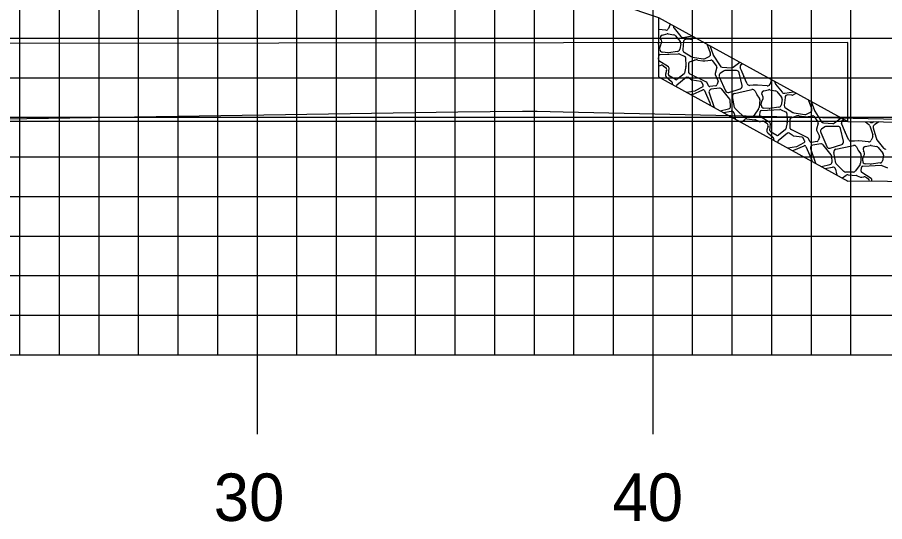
# Model space of a CAD drawing. Extents: x 856323 to 856666, y 364765 to 364985.
# Drawn here: x 856512.7 to 856534.62, y 364824.09 to 364836.83 of the extents above; entities that cross this region are included whole.
import ezdxf

# ---------------------------------------------------------------- set-up
doc = ezdxf.new("R2010")
doc.units = 0
for name, color, linetype in [('D_Drainage_Culvert', 7, 'Continuous'), ('D_Roadway_Centerline', 7, 'Continuous'), ('D_Roadway_FinishedGrade', 7, 'Continuous'), ('D_Roadway_SlopeLines', 7, 'Continuous'), ('H_V ANNOTATION', 7, 'Continuous'), ('MAJOR', 7, 'Continuous'), ('MINOR', 7, 'Continuous'), ('S_Roadway_Centerline', 7, 'Continuous')]:
    doc.layers.add(name, color=color, linetype=linetype)

msp = doc.modelspace()

# ---------------------------------------------------------------- linework, layer by layer
at = {"layer": 'D_Drainage_Culvert'}
msp.add_line((856533.694, 364834.192), (856476.17, 364834.192), dxfattribs=at)
msp.add_lwpolyline([(856533.694, 364834.192), (856533.691, 364836.192), (856476.17, 364836.121)], dxfattribs=at)
at = {"layer": 'D_Roadway_Centerline'}
msp.add_lwpolyline([(856476.17, 364847.458), (856483.623, 364847.116), (856488.768, 364846.88), (856491.27, 364846.765), (856496.768, 364846.512), (856500.528, 364845.572), (856508.768, 364843.512), (856509.507, 364843.328), (856509.84, 364843.244), (856518.287, 364840.401), (856528.903, 364836.827)], dxfattribs=at)
at = {"layer": 'D_Roadway_FinishedGrade'}
for p, q in [((856529.193, 364836.628), (856529.156, 364836.544)), ((856529.273, 364836.623), (856529.287, 364836.573)), ((856529.088, 364836.503), (856528.903, 364836.518)), ((856529.002, 364836.38), (856529.126, 364836.408)), ((856529.153, 364836.408), (856529.292, 364836.383)), ((856529.3, 364836.55), (856529.466, 364836.344)), ((856529.332, 364836.36), (856529.452, 364836.217)), ((856529.531, 364836.319), (856529.755, 364836.358)), ((856528.904, 364836.149), (856528.903, 364836.131)), ((856528.953, 364836.112), (856528.984, 364836.182)), ((856528.978, 364836.248), (856528.96, 364836.276)), ((856529.467, 364836.161), (856529.443, 364836.022)), ((856529.54, 364836.213), (856529.522, 364836.011)), ((856529.714, 364836.271), (856529.611, 364836.275)), ((856529.826, 364836.319), (856529.747, 364836.279)), ((856530.217, 364835.924), (856530.135, 364836.149)), ((856528.941, 364836.019), (856528.948, 364836.091)), ((856528.944, 364835.885), (856529.411, 364835.907)), ((856529.14, 364835.932), (856529.003, 364835.944)), ((856529.385, 364835.966), (856529.156, 364835.933)), ((856529.554, 364835.947), (856529.734, 364835.835)), ((856530.202, 364836.112), (856530.283, 364835.883)), ((856528.903, 364835.772), (856528.911, 364835.854)), ((856529.157, 364835.575), (856528.917, 364835.725)), ((856529.427, 364835.904), (856529.57, 364835.84)), ((856529.59, 364835.81), (856529.596, 364835.59)), ((856529.692, 364835.701), (856529.815, 364835.742)), ((856529.76, 364835.825), (856530.042, 364835.781)), ((856529.898, 364835.749), (856530.023, 364835.728)), ((856530.075, 364835.727), (856530.232, 364835.749)), ((856530.084, 364835.788), (856530.184, 364835.839)), ((856530.264, 364835.736), (856530.372, 364835.594)), ((856530.29, 364835.869), (856530.461, 364835.6)), ((856530.793, 364835.568), (856530.958, 364835.697)), ((856528.922, 364835.605), (856528.971, 364835.615)), ((856529.023, 364835.605), (856529.083, 364835.563)), ((856529.11, 364835.488), (856529.082, 364835.392)), ((856529.158, 364835.379), (856529.173, 364835.543)), ((856529.596, 364835.582), (856529.561, 364835.42)), ((856529.673, 364835.429), (856529.669, 364835.668)), ((856530.378, 364835.564), (856530.336, 364835.409)), ((856530.547, 364835.468), (856530.465, 364835.412)), ((856530.515, 364835.568), (856530.747, 364835.554)), ((856530.877, 364835.48), (856530.586, 364835.481)), ((856531.001, 364835.482), (856530.971, 364835.554)), ((856531.059, 364835.339), (856531.001, 364835.482)), ((856531.008, 364835.643), (856531.035, 364835.654)), ((856529.103, 364835.321), (856529.236, 364835.208)), ((856529.334, 364835.253), (856529.175, 364835.347)), ((856529.602, 364835.309), (856529.369, 364835.112)), ((856529.55, 364835.401), (856529.373, 364835.256)), ((856529.744, 364835.243), (856529.643, 364835.312)), ((856530.118, 364835.193), (856529.692, 364835.399)), ((856530.338, 364835.385), (856530.409, 364835.233)), ((856530.442, 364835.328), (856530.6, 364834.969)), ((856531.018, 364835.104), (856530.943, 364835.427)), ((856531.147, 364835.148), (856531.06, 364835.336)), ((856529.257, 364835.137), (856529.256, 364835.132)), ((856529.356, 364835.085), (856529.357, 364835.077)), ((856529.972, 364835.206), (856529.758, 364835.237)), ((856529.838, 364834.975), (856530.02, 364835.071)), ((856530.035, 364835.117), (856529.997, 364835.188)), ((856530.169, 364835.098), (856530.135, 364835.176)), ((856530.352, 364835.1), (856530.205, 364835.078)), ((856530.444, 364835.037), (856530.239, 364835.009)), ((856530.41, 364835.207), (856530.379, 364835.122)), ((856531.297, 364835.111), (856531.211, 364835.108)), ((856531.399, 364835.114), (856531.297, 364835.111)), ((856531.651, 364835.094), (856531.407, 364835.114)), ((856531.756, 364835.218), (856531.719, 364835.134)), ((856531.836, 364835.214), (856531.85, 364835.164)), ((856531.863, 364835.14), (856532.029, 364834.934)), ((856529.615, 364834.935), (856529.828, 364834.972)), ((856529.725, 364834.875), (856529.752, 364834.876)), ((856529.764, 364834.879), (856530.023, 364834.993)), ((856530.068, 364834.975), (856530.203, 364834.668)), ((856530.184, 364834.919), (856530.311, 364834.552)), ((856530.705, 364834.761), (856530.507, 364835.011)), ((856530.683, 364834.931), (856530.972, 364835.023)), ((856530.828, 364834.553), (856530.774, 364834.824)), ((856530.827, 364834.904), (856531.232, 364834.993)), ((856531.232, 364834.993), (856531.268, 364835.001)), ((856531.345, 364834.964), (856531.387, 364834.878)), ((856531.394, 364834.866), (856531.453, 364834.789)), ((856531.541, 364834.838), (856531.522, 364834.867)), ((856531.565, 364834.971), (856531.689, 364834.998)), ((856531.716, 364834.999), (856531.855, 364834.973)), ((856531.895, 364834.95), (856532.015, 364834.808)), ((856532.094, 364834.91), (856532.318, 364834.949)), ((856532.276, 364834.862), (856532.174, 364834.866)), ((856532.389, 364834.91), (856532.31, 364834.87)), ((856530.205, 364834.663), (856530.22, 364834.602)), ((856530.729, 364834.586), (856530.719, 364834.723)), ((856531.467, 364834.74), (856531.446, 364834.548)), ((856531.503, 364834.61), (856531.51, 364834.682)), ((856531.516, 364834.703), (856531.547, 364834.773)), ((856532.03, 364834.752), (856532.005, 364834.612)), ((856532.103, 364834.804), (856532.085, 364834.602)), ((856532.78, 364834.514), (856532.698, 364834.74)), ((856532.765, 364834.703), (856532.846, 364834.473)), ((856530.464, 364834.468), (856530.676, 364834.515)), ((856530.549, 364834.422), (856530.741, 364834.454)), ((856530.819, 364834.399), (856530.841, 364834.283)), ((856530.928, 364834.44), (856530.848, 364834.516)), ((856531.028, 364834.345), (856530.928, 364834.44)), ((856531.435, 364834.517), (856531.325, 364834.354)), ((856531.464, 364834.349), (856531.474, 364834.445)), ((856531.507, 364834.475), (856531.974, 364834.498)), ((856531.703, 364834.523), (856531.566, 364834.535)), ((856531.948, 364834.557), (856531.719, 364834.524)), ((856531.99, 364834.495), (856532.132, 364834.431)), ((856532.117, 364834.538), (856532.297, 364834.425)), ((856532.152, 364834.401), (856532.159, 364834.181)), ((856532.323, 364834.416), (856532.605, 364834.372)), ((856532.646, 364834.378), (856532.747, 364834.43)), ((856532.853, 364834.459), (856533.024, 364834.19)), ((856530.841, 364834.283), (856530.846, 364834.258)), ((856530.995, 364834.177), (856531.086, 364834.247)), ((856531.267, 364834.324), (856531.074, 364834.327)), ((856531.135, 364834.261), (856531.342, 364834.238)), ((856531.36, 364834.234), (856531.446, 364834.2)), ((856531.719, 364834.166), (856531.48, 364834.316)), ((856531.485, 364834.196), (856531.533, 364834.206)), ((856531.586, 364834.196), (856531.646, 364834.154)), ((856532.158, 364834.173), (856532.124, 364834.011)), ((856532.236, 364834.02), (856532.231, 364834.259)), ((856532.255, 364834.292), (856532.378, 364834.333)), ((856532.461, 364834.34), (856532.586, 364834.318)), ((856532.638, 364834.317), (856532.795, 364834.339)), ((856532.827, 364834.326), (856532.935, 364834.185)), ((856532.941, 364834.155), (856532.899, 364833.999)), ((856533.078, 364834.159), (856533.309, 364834.145)), ((856533.355, 364834.159), (856533.52, 364834.287)), ((856533.57, 364834.233), (856533.598, 364834.245)), ((856534.137, 364834.188), (856534.222, 364834.12)), ((856534.249, 364834.187), (856534.249, 364834.187)), ((856534.349, 364834.186), (856534.333, 364834.177)), ((856534.473, 364834.185), (856534.36, 364834.108)), ((856531.673, 364834.078), (856531.645, 364833.983)), ((856531.721, 364833.97), (856531.735, 364834.134)), ((856531.897, 364833.843), (856531.738, 364833.938)), ((856532.112, 364833.991), (856531.936, 364833.846)), ((856532.681, 364833.783), (856532.255, 364833.99)), ((856532.901, 364833.976), (856532.972, 364833.824)), ((856533.11, 364834.059), (856533.028, 364834.003)), ((856533.44, 364834.071), (856533.149, 364834.071)), ((856533.581, 364833.695), (856533.506, 364834.018)), ((856533.564, 364834.073), (856533.534, 364834.144)), ((856533.622, 364833.93), (856533.564, 364834.073)), ((856534.245, 364834.088), (856534.321, 364833.858)), ((856534.332, 364834.033), (856534.399, 364833.805)), ((856531.666, 364833.912), (856531.799, 364833.799)), ((856531.82, 364833.728), (856531.819, 364833.723)), ((856532.165, 364833.9), (856531.931, 364833.703)), ((856532.306, 364833.834), (856532.206, 364833.902)), ((856532.535, 364833.797), (856532.321, 364833.828)), ((856532.597, 364833.707), (856532.56, 364833.779)), ((856532.731, 364833.688), (856532.697, 364833.766)), ((856532.973, 364833.797), (856532.942, 364833.713)), ((856533.004, 364833.919), (856533.163, 364833.56)), ((856533.709, 364833.739), (856533.623, 364833.927)), ((856534.319, 364833.809), (856534.282, 364833.725)), ((856534.399, 364833.805), (856534.413, 364833.755)), ((856534.425, 364833.731), (856534.591, 364833.525)), ((856531.919, 364833.676), (856531.919, 364833.668)), ((856532.178, 364833.526), (856532.39, 364833.563)), ((856532.327, 364833.47), (856532.585, 364833.584)), ((856532.4, 364833.566), (856532.583, 364833.661)), ((856532.631, 364833.566), (856532.766, 364833.259)), ((856532.747, 364833.51), (856532.873, 364833.143)), ((856532.915, 364833.691), (856532.768, 364833.668)), ((856533.007, 364833.628), (856532.802, 364833.6)), ((856533.268, 364833.351), (856533.07, 364833.602)), ((856533.246, 364833.522), (856533.535, 364833.614)), ((856533.389, 364833.495), (856533.795, 364833.584)), ((856533.86, 364833.702), (856533.774, 364833.699)), ((856533.795, 364833.584), (856533.831, 364833.592)), ((856533.961, 364833.705), (856533.86, 364833.702)), ((856533.907, 364833.555), (856533.95, 364833.469)), ((856534.213, 364833.684), (856533.969, 364833.705)), ((856534.127, 364833.562), (856534.252, 364833.589)), ((856534.279, 364833.59), (856534.418, 364833.564)), ((856534.458, 364833.541), (856534.578, 364833.399)), ((856532.287, 364833.465), (856532.314, 364833.467)), ((856533.292, 364833.177), (856533.282, 364833.314)), ((856533.391, 364833.144), (856533.337, 364833.415)), ((856533.957, 364833.457), (856534.016, 364833.379)), ((856534.03, 364833.33), (856534.009, 364833.139)), ((856534.079, 364833.293), (856534.109, 364833.364)), ((856534.104, 364833.429), (856534.085, 364833.457)), ((856534.593, 364833.343), (856534.568, 364833.203)), ((856532.768, 364833.254), (856532.783, 364833.193)), ((856533.027, 364833.059), (856533.238, 364833.105)), ((856533.491, 364833.031), (856533.41, 364833.107)), ((856533.998, 364833.108), (856533.888, 364832.945)), ((856534.066, 364833.2), (856534.073, 364833.272)), ((856534.069, 364833.066), (856534.537, 364833.089)), ((856534.266, 364833.114), (856534.128, 364833.126)), ((856534.511, 364833.147), (856534.282, 364833.114)), ((856534.553, 364833.086), (856534.695, 364833.022)), ((856533.111, 364833.012), (856533.304, 364833.045)), ((856533.382, 364832.99), (856533.404, 364832.874)), ((856533.404, 364832.874), (856533.409, 364832.849)), ((856533.591, 364832.936), (856533.491, 364833.031)), ((856533.558, 364832.768), (856533.648, 364832.838)), ((856533.83, 364832.915), (856533.637, 364832.917)), ((856533.697, 364832.851), (856533.905, 364832.829)), ((856534.027, 364832.94), (856534.037, 364833.036)), ((856534.282, 364832.756), (856534.042, 364832.907)), ((856533.923, 364832.824), (856534.009, 364832.79)), ((856534.047, 364832.787), (856534.096, 364832.797)), ((856534.149, 364832.786), (856534.209, 364832.745)), ((856534.295, 364832.687), (856534.298, 364832.724))]:
    msp.add_line(p, q, dxfattribs=at)
for centre, radius, start, end in [((856529.13, 364836.655), 0.0684, 336.3884, 7.7757), ((856529.353, 364836.593), 0.0684, 196.194, 218.8878), ((856529.017, 364836.314), 0.0684, 102.3799, 213.4945), ((856529.094, 364836.571), 0.0684, 265.1565, 336.3884), ((856529.141, 364836.341), 0.0684, 79.6289, 102.3799), ((856529.28, 364836.315), 0.0684, 40.2205, 79.6289), ((856529.519, 364836.387), 0.0684, 218.8878, 279.8538), ((856528.836, 364836.156), 0.0684, 353.6734, 15.0307), ((856528.921, 364836.21), 0.0684, 336.3884, 33.4945), ((856529.4, 364836.173), 0.0684, 349.9353, 40.2205), ((856529.608, 364836.207), 0.0684, 87.759, 174.9435), ((856529.716, 364836.34), 0.0684, 267.759, 296.9783), ((856529.009, 364836.012), 0.0684, 174.5792, 265.0542), ((856529.016, 364836.084), 0.0684, 156.3884, 174.5792), ((856529.146, 364836), 0.0684, 265.0542, 278.2139), ((856529.375, 364836.034), 0.0684, 278.2139, 349.9353), ((856529.413, 364835.873), 0.0342, 65.8608, 92.7454), ((856529.59, 364836.005), 0.0684, 174.9435, 237.9695), ((856530.153, 364835.9), 0.0684, 297.1975, 20.0877), ((856528.935, 364835.754), 0.0342, 197.9909, 237.8666), ((856528.945, 364835.851), 0.0342, 92.7454, 173.8138), ((856529.556, 364835.809), 0.0342, 1.7042, 65.8608), ((856529.703, 364835.669), 0.0342, 108.5155, 180.9859), ((856529.771, 364835.892), 0.0684, 237.9695, 261.1196), ((856529.869, 364835.58), 0.171, 80.3276, 108.5155), ((856530.052, 364835.896), 0.171, 260.3276, 277.9584), ((856530.052, 364835.848), 0.0684, 261.1196, 297.1975), ((856530.237, 364835.715), 0.0342, 37.3338, 97.9584), ((856530.348, 364835.905), 0.0684, 199.4352, 212.488), ((856528.908, 364835.672), 0.0684, 265.2397, 281.5585), ((856528.984, 364835.548), 0.0684, 55.4834, 101.5585), ((856529.045, 364835.507), 0.0684, 343.6014, 55.4834), ((856529.139, 364835.546), 0.0342, 354.9435, 57.8666), ((856529.562, 364835.589), 0.0342, 348.1215, 1.7042), ((856530.345, 364835.573), 0.0342, 344.9548, 37.3338), ((856530.519, 364835.636), 0.0684, 212.488, 266.5979), ((856530.586, 364835.412), 0.0684, 89.9515, 124.6871), ((856530.751, 364835.622), 0.0684, 266.5979, 307.8384), ((856530.877, 364835.412), 0.0684, 13.0274, 89.9515), ((856531.035, 364835.58), 0.0684, 113.1469, 202.5342), ((856530.938, 364835.456), 0.0684, 22.1001, 22.5342), ((856529.148, 364835.373), 0.0684, 163.6014, 229.5603), ((856529.192, 364835.376), 0.0342, 174.9435, 239.3161), ((856529.351, 364835.282), 0.0342, 239.3161, 309.3926), ((856529.528, 364835.427), 0.0342, 309.3926, 348.1215), ((856529.624, 364835.283), 0.0342, 55.6218, 130.2011), ((856529.707, 364835.43), 0.0342, 180.9859, 244.1843), ((856530.369, 364835.4), 0.0342, 164.9548, 204.8803), ((856530.504, 364835.356), 0.0684, 124.6871, 203.8307), ((856531.122, 364835.365), 0.0684, 202.1001, 204.6651), ((856531.693, 364835.246), 0.0684, 336.3884, 7.7757), ((856529.192, 364835.156), 0.0684, 344.328, 49.5603), ((856529.391, 364835.086), 0.0342, 130.2011, 181.8446), ((856529.763, 364835.271), 0.0342, 235.6218, 261.6774), ((856529.967, 364835.172), 0.0342, 27.5039, 81.6774), ((856530.004, 364835.101), 0.0342, 297.5039, 27.5039), ((856530.103, 364835.162), 0.0342, 23.6254, 64.1843), ((856530.2, 364835.111), 0.0342, 203.6254, 278.7288), ((856530.347, 364835.134), 0.0342, 278.7288, 339.9401), ((856530.378, 364835.218), 0.0342, 339.9401, 24.8803), ((856530.454, 364834.969), 0.0684, 38.1718, 97.8011), ((856530.952, 364835.088), 0.0684, 287.6261, 13.0274), ((856531.209, 364835.177), 0.0684, 204.6651, 271.8446), ((856531.401, 364835.046), 0.0684, 85.1565, 91.8446), ((856531.656, 364835.162), 0.0684, 265.1565, 336.3884), ((856531.916, 364835.183), 0.0684, 196.194, 218.8878), ((856529.75, 364834.91), 0.0342, 272.567, 293.7886), ((856529.822, 364835.006), 0.0342, 279.9682, 297.5039), ((856530.037, 364834.962), 0.0342, 23.7886, 113.7886), ((856530.249, 364834.941), 0.0684, 97.8011, 199.0716), ((856530.663, 364834.997), 0.0684, 203.8307, 287.6261), ((856530.841, 364834.837), 0.0684, 102.451, 191.1515), ((856531.283, 364834.934), 0.0684, 25.9764, 102.451), ((856531.448, 364834.908), 0.0684, 205.9764, 217.5646), ((856531.579, 364834.904), 0.0684, 102.3799, 213.4945), ((856531.484, 364834.801), 0.0684, 336.3884, 33.4945), ((856531.704, 364834.932), 0.0684, 79.6289, 102.3799), ((856531.843, 364834.906), 0.0684, 40.2205, 79.6289), ((856532.082, 364834.977), 0.0684, 218.8878, 279.8538), ((856532.171, 364834.798), 0.0684, 87.759, 174.9435), ((856532.279, 364834.931), 0.0684, 267.759, 296.9783), ((856530.172, 364834.655), 0.0342, 13.983, 23.7886), ((856530.651, 364834.718), 0.0684, 4.1565, 38.1718), ((856531.399, 364834.747), 0.0684, 353.6734, 37.5646), ((856531.572, 364834.603), 0.0684, 174.5792, 265.0542), ((856531.578, 364834.675), 0.0684, 156.3884, 174.5792), ((856531.938, 364834.624), 0.0684, 278.2139, 349.9353), ((856531.963, 364834.764), 0.0684, 349.9353, 40.2205), ((856532.153, 364834.596), 0.0684, 174.9435, 237.9695), ((856530.661, 364834.581), 0.0684, 282.4402, 4.1565), ((856530.752, 364834.387), 0.0684, 10.6652, 99.567), ((856530.895, 364834.566), 0.0684, 191.1515, 226.4504), ((856531.378, 364834.555), 0.0684, 325.9996, 353.6734), ((856531.508, 364834.441), 0.0342, 92.7454, 173.8138), ((856531.709, 364834.591), 0.0684, 265.0542, 278.2139), ((856531.976, 364834.464), 0.0342, 65.8608, 92.7454), ((856532.118, 364834.4), 0.0342, 1.7042, 65.8608), ((856532.333, 364834.483), 0.0684, 237.9695, 261.1196), ((856532.615, 364834.439), 0.0684, 261.1196, 297.1975), ((856532.716, 364834.491), 0.0684, 297.1975, 20.0877), ((856532.911, 364834.496), 0.0684, 199.4352, 212.488), ((856531.037, 364834.123), 0.0684, 127.5119, 128.402), ((856531.075, 364834.395), 0.0684, 226.4504, 269.2665), ((856531.127, 364834.193), 0.0684, 83.8138, 127.5119), ((856531.268, 364834.392), 0.0684, 269.2665, 325.9996), ((856531.335, 364834.17), 0.0684, 68.319, 83.8138), ((856531.471, 364834.263), 0.0684, 248.319, 281.5585), ((856531.498, 364834.345), 0.0342, 173.8138, 237.8666), ((856531.547, 364834.139), 0.0684, 55.4834, 101.5585), ((856531.607, 364834.098), 0.0684, 343.6014, 55.4834), ((856531.701, 364834.137), 0.0342, 354.9435, 57.8666), ((856532.125, 364834.18), 0.0342, 348.1215, 1.7042), ((856532.266, 364834.259), 0.0342, 108.5155, 180.9859), ((856532.432, 364834.171), 0.171, 80.3276, 108.5155), ((856532.614, 364834.487), 0.171, 260.3276, 277.9584), ((856532.8, 364834.306), 0.0342, 37.3338, 97.9584), ((856532.908, 364834.164), 0.0342, 344.9548, 37.3338), ((856533.082, 364834.227), 0.0684, 212.488, 266.5979), ((856533.313, 364834.213), 0.0684, 266.5979, 307.8384), ((856533.597, 364834.171), 0.0684, 113.1469, 202.5342), ((856534.298, 364834.235), 0.0684, 225.2486, 301.0205), ((856531.711, 364833.964), 0.0684, 163.6014, 229.5603), ((856531.755, 364833.967), 0.0342, 174.9435, 239.3161), ((856532.091, 364834.018), 0.0342, 309.3926, 348.1215), ((856532.27, 364834.02), 0.0342, 180.9859, 244.1843), ((856532.932, 364833.99), 0.0342, 164.9548, 204.8803), ((856533.067, 364833.946), 0.0684, 124.6871, 203.8307), ((856533.149, 364834.003), 0.0684, 89.9515, 124.6871), ((856533.44, 364834.003), 0.0684, 13.0274, 89.9515), ((856533.501, 364834.047), 0.0684, 22.1001, 22.5342), ((856534.18, 364834.067), 0.0684, 18.3151, 51.3282), ((856534.398, 364834.052), 0.0684, 124.1631, 196.194), ((856531.754, 364833.747), 0.0684, 344.328, 49.5603), ((856531.914, 364833.873), 0.0342, 239.3161, 309.3926), ((856532.187, 364833.874), 0.0342, 55.6218, 130.2011), ((856532.326, 364833.862), 0.0342, 235.6218, 261.6774), ((856532.53, 364833.763), 0.0342, 27.5039, 81.6774), ((856532.666, 364833.753), 0.0342, 23.6254, 64.1843), ((856532.91, 364833.725), 0.0342, 278.7288, 339.9401), ((856532.941, 364833.809), 0.0342, 339.9401, 24.8803), ((856533.685, 364833.956), 0.0684, 202.1001, 204.6651), ((856533.772, 364833.767), 0.0684, 204.6651, 271.8446), ((856534.219, 364833.752), 0.0684, 265.1565, 336.3884), ((856534.256, 364833.837), 0.0684, 336.3884, 7.7757), ((856534.256, 364833.837), 0.0684, 7.7757, 18.3151), ((856534.479, 364833.774), 0.0684, 196.194, 218.8878), ((856531.953, 364833.677), 0.0342, 130.2011, 181.8446), ((856532.385, 364833.597), 0.0342, 279.9682, 297.5039), ((856532.567, 364833.692), 0.0342, 297.5039, 27.5039), ((856532.599, 364833.552), 0.0342, 23.7886, 113.7886), ((856532.763, 364833.702), 0.0342, 203.6254, 278.7288), ((856532.811, 364833.532), 0.0684, 97.8011, 199.0716), ((856533.017, 364833.56), 0.0684, 38.1718, 97.8011), ((856533.225, 364833.587), 0.0684, 203.8307, 287.6261), ((856533.404, 364833.428), 0.0684, 102.451, 191.1515), ((856533.514, 364833.679), 0.0684, 287.6261, 13.0274), ((856533.846, 364833.525), 0.0684, 25.9764, 102.451), ((856533.964, 364833.637), 0.0684, 85.1565, 91.8446), ((856534.142, 364833.495), 0.0684, 102.3799, 213.4945), ((856534.267, 364833.522), 0.0684, 79.6289, 102.3799), ((856534.405, 364833.497), 0.0684, 40.2205, 79.6289), ((856534.645, 364833.568), 0.0684, 218.8878, 279.8538), ((856532.313, 364833.501), 0.0342, 272.567, 293.7886), ((856533.214, 364833.309), 0.0684, 4.1565, 38.1718), ((856534.011, 364833.498), 0.0684, 205.9764, 217.5646), ((856533.962, 364833.338), 0.0684, 353.6734, 37.5646), ((856534.141, 364833.266), 0.0684, 156.3884, 174.5792), ((856534.047, 364833.391), 0.0684, 336.3884, 33.4945), ((856534.526, 364833.355), 0.0684, 349.9353, 40.2205), ((856532.735, 364833.245), 0.0342, 13.983, 23.7886), ((856533.224, 364833.172), 0.0684, 282.4402, 4.1565), ((856533.458, 364833.157), 0.0684, 191.1515, 226.4504), ((856533.941, 364833.146), 0.0684, 325.9996, 353.6734), ((856534.071, 364833.032), 0.0342, 92.7454, 173.8138), ((856534.134, 364833.194), 0.0684, 174.5792, 265.0542), ((856534.272, 364833.182), 0.0684, 265.0542, 278.2139), ((856534.501, 364833.215), 0.0684, 278.2139, 349.9353), ((856534.539, 364833.054), 0.0342, 65.8608, 92.7454), ((856533.315, 364832.977), 0.0684, 10.6652, 99.567), ((856533.638, 364832.986), 0.0684, 226.4504, 269.2665), ((856533.69, 364832.783), 0.0684, 83.8138, 127.5119), ((856533.831, 364832.983), 0.0684, 269.2665, 325.9996), ((856534.061, 364832.936), 0.0342, 173.8138, 237.8666), ((856533.599, 364832.714), 0.0684, 127.5119, 128.402), ((856533.898, 364832.761), 0.0684, 68.319, 83.8138), ((856534.034, 364832.854), 0.0684, 248.319, 281.5585), ((856534.11, 364832.73), 0.0684, 55.4834, 101.5585), ((856534.17, 364832.688), 0.0684, 358.9754, 55.4834), ((856534.264, 364832.727), 0.0342, 354.9435, 57.8666)]:
    msp.add_arc(centre, radius, start, end, dxfattribs=at)
at = {"layer": 'D_Roadway_SlopeLines'}
msp.add_line((856528.903, 364836.827), (856533.694, 364834.192), dxfattribs=at)
for points in [[(856528.903, 364836.827), (856528.903, 364835.327), (856533.694, 364832.692)], [(856533.694, 364834.192), (856542.694, 364834.109), (856542.694, 364832.609), (856533.694, 364832.692)]]:
    msp.add_lwpolyline(points, dxfattribs=at)
at = {"layer": 'MAJOR'}
for p, q in [((856518.768, 364828.302), (856518.768, 364853.302)), ((856528.768, 364828.302), (856528.768, 364853.302)), ((856348.768, 364833.302), (856628.768, 364833.302)), ((856348.768, 364828.302), (856628.768, 364828.302)), ((856348.768, 364828.302), (856628.768, 364828.302)), ((856518.768, 364826.298), (856518.768, 364828.302)), ((856528.768, 364826.298), (856528.768, 364828.302))]:
    msp.add_line(p, q, dxfattribs=at)
at = {"layer": 'MINOR'}
for p, q in [((856512.768, 364828.302), (856512.768, 364853.302)), ((856513.768, 364828.302), (856513.768, 364853.302)), ((856514.768, 364828.302), (856514.768, 364853.302)), ((856515.768, 364828.302), (856515.768, 364853.302)), ((856516.768, 364828.302), (856516.768, 364853.302)), ((856517.768, 364828.302), (856517.768, 364853.302)), ((856519.768, 364828.302), (856519.768, 364853.302)), ((856520.768, 364828.302), (856520.768, 364853.302)), ((856521.768, 364828.302), (856521.768, 364853.302)), ((856522.768, 364828.302), (856522.768, 364853.302)), ((856523.768, 364828.302), (856523.768, 364853.302)), ((856524.768, 364828.302), (856524.768, 364853.302)), ((856525.768, 364828.302), (856525.768, 364853.302)), ((856526.768, 364828.302), (856526.768, 364853.302)), ((856527.768, 364828.302), (856527.768, 364853.302)), ((856529.768, 364828.302), (856529.768, 364853.302)), ((856530.768, 364828.302), (856530.768, 364853.302)), ((856531.768, 364828.302), (856531.768, 364853.302)), ((856532.768, 364828.302), (856532.768, 364853.302)), ((856533.768, 364828.302), (856533.768, 364853.302)), ((856348.768, 364836.302), (856628.768, 364836.302)), ((856348.768, 364835.302), (856628.768, 364835.302)), ((856348.768, 364834.302), (856628.768, 364834.302)), ((856348.768, 364832.302), (856628.768, 364832.302)), ((856348.768, 364831.302), (856628.768, 364831.302)), ((856348.768, 364830.302), (856628.768, 364830.302)), ((856348.768, 364829.302), (856628.768, 364829.302))]:
    msp.add_line(p, q, dxfattribs=at)
at = {"layer": 'S_Roadway_Centerline'}
msp.add_lwpolyline([(856468.17, 364834.44), (856477.631, 364834.392), (856488.091, 364834.229), (856493.984, 364834.166), (856502.233, 364834.138), (856506.394, 364834.174), (856523.832, 364834.442), (856525.471, 364834.453), (856525.841, 364834.454), (856526.497, 364834.44), (856538.058, 364834.187), (856544.846, 364834.073), (856550.24, 364834.018), (856559.769, 364833.685), (856562.105, 364833.634), (856563.443, 364833.597), (856571.424, 364833.699)], dxfattribs=at)

# ---------------------------------------------------------------- texts
at = {"layer": 'H_V ANNOTATION'}
for s, p in [('30', (856517.666, 364824.102)), ('40', (856527.741, 364824.102))]:
    msp.add_text(s, height=1.2, dxfattribs=at).set_placement(p)

doc.saveas('drawing.dxf')
